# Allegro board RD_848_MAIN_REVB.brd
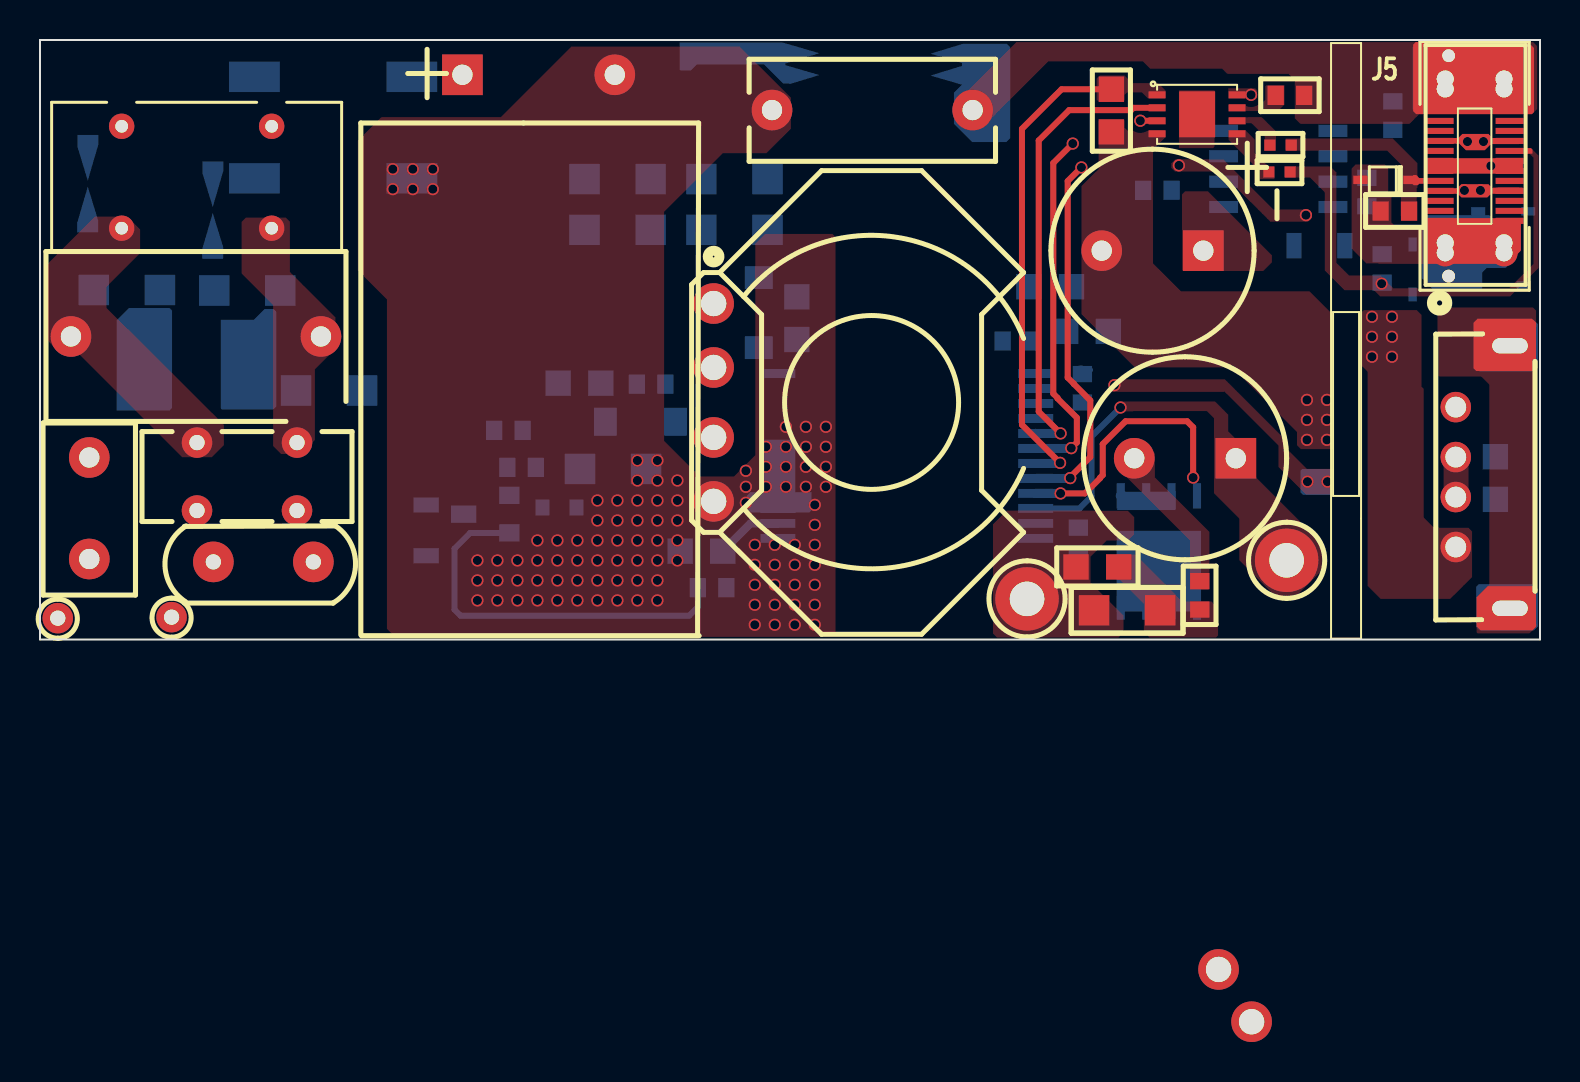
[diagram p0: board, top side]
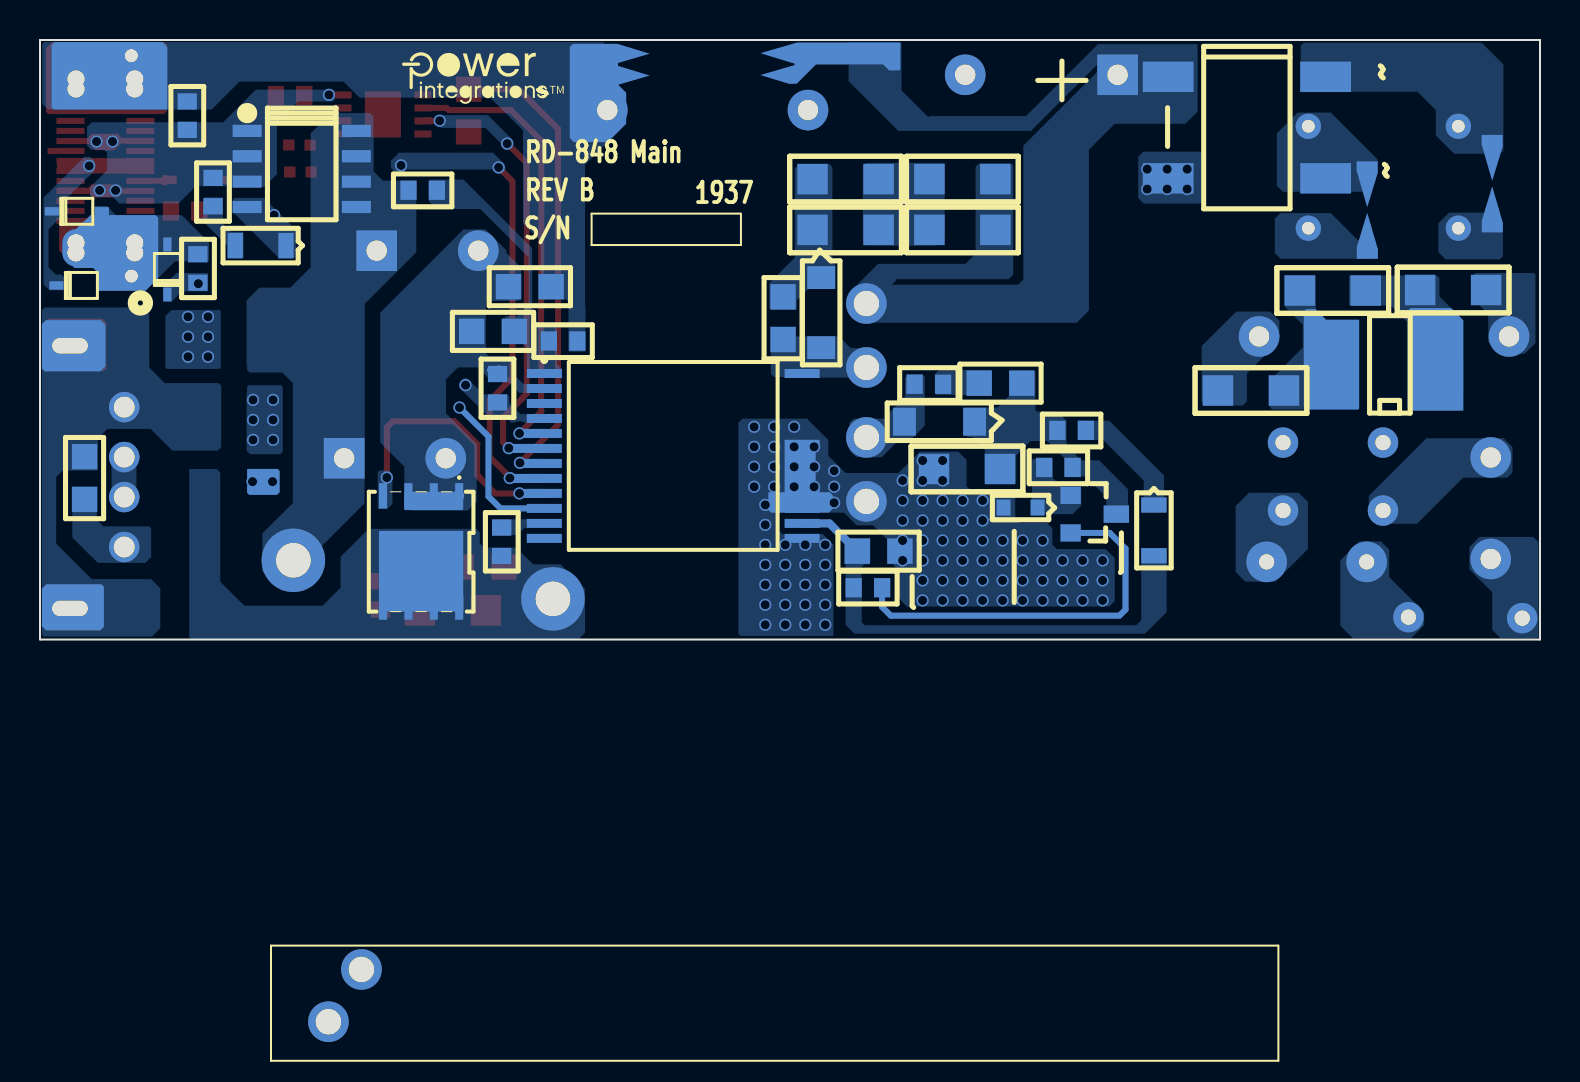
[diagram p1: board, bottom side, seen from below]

Outline 75 x 30 mm; copper layers: TOP, BOTTOM. Coordinates in mm from the lower left corner of the outline.
Outline path: 0,30 0,0 75,0 75,30 0,30

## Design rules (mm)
constraint set DEFAULT: min track width 0.3

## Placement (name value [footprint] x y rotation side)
BR1  DF206ST-G  [PISMDDFS]  18.54 28.16 90 bottom
C1  68 uF  [PIPOLCAPCLYD630LS300040]  21.12 28.26 0 top
C4  10 uF  [PISMC1206]  27 8.53 0 bottom
C5  1  nF  [PISMC1206]  27.23 23.04 0 bottom
C6  4.7 uF  [PISMC0805]  34.14 4.42 180 bottom
C7  47 pF  [PISMC0805]  37.85 17.14 270 bottom
C8  220 pF  [PISMC0603]  29.84 12.78 0 bottom
C11  1000 pF  [PISMC0603]  57.99 2.92 270 top
C12  390 uF  [PIPOLCAPCYLD400LS200040]  58.17 19.46 180 top
C13  390 uF  [PIPOLCAPCYLD400LS200040]  59.79 9.07 180 top
C14  2.2 uF  [PISMC0603]  52.12 13.28 270 bottom
C15  4.7 uF  [PISMC0805]  53.42 15.42 180 bottom
C17  2.2 uF  [PISMC0805]  53.57 25.4 90 top
C27  1 uF  [PISMC0603]  67.64 25.5 90 bottom
C28  560 pF  [PISMC0603]  68.45 21.44 180 top
C29  560 pF  [PISMC0603]  67.11 17.86 90 bottom
C49  0.1 uF  [PISMC0805]  72.77 7.01 90 bottom
CX1  330 nF  [PINP_XCAPRAD15X8P5X14HD040]  14.05 15.16 180 top
CY1  1 nF  [PI_NP475X200LS395D040]  36.6 26.49 0 top
D1  S1ML  [PI_SM_SOD-123_12]  35.94 18.11 270 bottom
D2  S1ML  [PI_SM_SOD-123_12]  28.27 10.9 0 bottom
D3  BAV19WS  [PISMSOD323]  62.7 19.71 0 bottom
D6  MM3Z24VC  [PISMSOD323F]  74.18 17.72 180 bottom
D7  MM3Z24VC  [PISMSOD323F]  74.41 21.43 180 bottom
D8  MM3Z24VC  [PISMSOD323F]  68.52 23 180 top
D9  MM3Z24VC  [PISMSOD323F]  68.63 17.27 90 bottom
F1  3.15 A  [PI_RST_MICROFUSE]  2.46 4.03 90 top
FL1  Hole_70mils  [PI_HOLE_70MIL]  62.33 3.94 0 top
FL2  Hole_70mils  [PI_HOLE_70MIL]  49.35 2.01 0 top
J1  PCB Terminal 30 AWG  [PI_HOLE_30AWG]  0.89 1.07 0 top
J2  PCB Terminal 30 AWG  [PI_HOLE_30AWG]  6.58 1.12 0 top
J4  CON4  [PI_CONN_USB4P_VERT_WURTH]  70.79 8.13 180 top
J5  USB-C  [PI_DX07S024WJ3R400]  69.98 20.95 90 top
L1  550 uH  [PI_4P_LS5W4P5XD10P5MMD40]  10.35 8.15 90 top
L2  20 mH  [PI_TOROID_CMC12P5X7P5_4PV]  11.58 19.38 270 top
NOREF  -  []  -228.6 -144.78 0 top
NOREF#2  -  []  0 30 0 top
NOREF#3  -  []  0 0 90 top
NOREF#4  -  []  -150.78 54.23 0 top
NOREF#5  -  []  57.45 29.27 180 bottom
Q1  MMBTA06LT1G  [PISMSOT23123_1]  23.47 5.33 270 bottom
Q2  AON6220  [PISMPQFN5X6B]  54.04 7.19 0 bottom
Q4  AO4354  [PISMSO8]  64.64 25.45 270 bottom
R3  470 k  [PISMR1206]  27.23 20.5 0 bottom
R4  20  [PISMR1206]  36.37 20.5 180 bottom
R5  20  [PISMR1206]  36.37 23.04 180 bottom
R6  100 k  [PISMR0603]  23.37 8.61 0 bottom
R7  3 k  [PISMR0603]  32.89 2.59 0 bottom
R8  47  [PISMR0603]  24.13 10.46 180 bottom
R11  20  [PISMR0805]  53.94 3.63 180 top
R12  47  [PISMR0603]  51.92 4.18 90 bottom
R13  487 k  [PISMR0603]  56.58 22.48 180 bottom
R14  100  [PISMR0603]  66.34 23.1 270 bottom
R15  10  [PISMR0603]  49.56 14.94 180 bottom
R16  10  [PISMR0805]  25.91 12.83 0 bottom
R20  22  [PISMR0402]  62.56 24.74 180 top
R21  22  [PISMR0402]  62.51 23.39 180 top
R22  12  [PISMR1206]  56.01 1.46 180 top
R23  1 M  [PISMR1206]  2.69 17.49 0 bottom
R24  1 M  [PISMR1206]  12.8 12.46 0 bottom
R25  1 M  [PISMR1206]  8.71 17.46 0 bottom
RS1  0.009  [PISMR0805]  51.57 17.65 180 bottom
RT1  2.5  [PI_RAD150X300LS200D030]  8.67 3.88 0 top
RT2  100 k  [PISMR0603]  63.21 27.23 180 top
T1  RM8  [PI_BOBBIN_RM8_6P_813]  41.58 11.86 0 top
U1  InnoProSize9  [PI_IC_INSOP_24D]  49.78 13.31 180 bottom
U3  VP302  [PI_SM_DFN-8]  55.85 27.25 270 top
U4  CAP200DG *  [PI_IC_SMD_SO8_CAPZERO]  4.97 11.86 90 bottom
ZD1  EDZVT2R10B  [PI_SM_D_SSMINI2P]  25.12 6.6 0 bottom
ZD2  MM3Z47VB  [PISMSOD323]  19.3 6.73 270 bottom

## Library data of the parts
BR1 = DIODE BRIDGE_+-~~
C1 = CAP POL: alternate symbols: (pipolcapclyd630ls3000401000h)
C4 = CAP NP: alternate symbols: (pismc1206_1)
C5-C8 C11 C15 C17 C28 C29 C49 CY1 = CAP NP
C12 C13 = CAP POL: alternate symbols: (pipolcapclyd395x630ls200030h)
C14 C27 = CAP NP: alternate symbols: (pismc0603_1)
CX1 = CAP NP: alternate symbols: (pinp_xcaprad15x8p5x14Hd040H)
D1-D3 = DIODE
D6-D9 ZD1 ZD2 = DIODE_ZENER
F1 = FUSE: alternate symbols: (pirstmicrofusehoz)
FL1 FL2 = FlyingLead
J1 J2 = TERM_1Pin
J4 = CON4_USB_1
J5 = DX07S024WJ3R400: User Part Number: PN; Tolerance: TOL
L1 = TORRID 4P_12_0
L2 = TORRID 4P_12_43a
Q1 = NPN_BEC
Q2 Q4 = FET_N_SGD_123_4_5678
R3-R7 R11 R13-R16 R20-R25 RS1 = R
R8 R12 = R: alternate symbols: (pismr0603_1)
RT1 = THERMISTOR: alternate symbols: (pirad400x300ls200040_h)
RT2 = THERMISTOR
T1 = BRM8_6P/4-2
U1 = DEV_InnoPro
U3 = VP302
U4 = CAPZero

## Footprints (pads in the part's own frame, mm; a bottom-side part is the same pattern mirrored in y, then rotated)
PI_4P_LS5W4P5XD10P5MMD40
  round 1.524 hole 0.762: 1(-1.7,-2.5) 2(1.7,-2.5) 3(1.7,2.5) 4(-1.7,2.5)
PI_BOBBIN_RM8_6P_813
  round 2.032 hole 1.27: 1(-7.9,4.95) 2(-7.9,1.75) 3(-7.9,-1.75) 4(-7.9,-4.95) 5(18.999,-30.988) 6(17.348,-28.372)
PI_CONN_USB4P_VERT_WURTH
  oval 2.54x1.524 hole 1.778x0.762: (-2.71,6.57) (-2.71,-6.57)
  round 1.524 hole 1.041: 1(0,3.5) 2(0,1) 3(0,-1) 4(0,-3.5)
PI_DX07S024WJ3R400
  round 0.85 hole 0.85 unplated: (-1.6,-0.28) (-1.6,-3.22) (-1.1,-0.28) (-1.1,-3.22) (6.6,-0.28) (6.6,-3.22) (7.1,-0.28) (7.1,-3.22)
  oval 1.858x1.358 hole 0.025 unplated: (-1.35,-0.28) (-1.35,-3.22) (6.85,-0.28) (6.85,-3.22)
  round 0.635 hole 0.635: 25(-2.765,-0.45) 26(8.265,-0.45)
  rect 0.305x1.397 smd: A1(0,0) A2(0.5,0) A3(1,0) A4(1.5,0) A5(2,0) A6(2.5,0) A7(3,0) A8(3.5,0) A9(4,0) A10(4.5,0) A11(5,0) A12(5.5,0) B1(5.5,-3.5) B2(5,-3.5) B3(4.5,-3.5) B4(4,-3.5) B5(3.5,-3.5) B6(3,-3.5) B7(2.5,-3.5) B8(2,-3.5) B9(1.5,-3.5) B10(1,-3.5) B11(0.5,-3.5) B12(0,-3.5)
PI_HOLE_30AWG
  round 1.524 hole 0.762: 1(0,0)
PI_HOLE_70MIL
  round 3.175 hole 1.727: 1(0,0.025)
PI_IC_INSOP_24D
  rect 1.75x0.45 smd: 1(0,0) 2(0,-0.75) 3(0,-1.5) 4(0,-2.25) 5(0,-3) 6(0,-3.75) 7(0,-4.5) 8(0,-5.25) 9(0,-6) 10(0,-6.75) 11(0,-7.5) 12(0,-8.25) 13(12.89,-8.25) 14(12.89,-7.5) 15(12.89,-6.75) 24(12.89,0)
  custom 0.438x0.438 smd: 16(12.89,-4.67)
PI_IC_SMD_SO8_CAPZERO
  rect 0.599x2.2 smd: 1(0,0) 2(1.27,0) 3(2.54,0) 4(3.81,0) 5(3.81,5.199) 6(2.54,5.199) 7(1.27,5.199) 8(0,5.199)
PI_NP475X200LS395D040
  round 2.032 hole 1.016: 1(0,0) 2(10.033,0)
PI_RAD150X300LS200D030
  round 2.032 hole 0.762: 1(0,0) 2(5,0)
PI_RST_MICROFUSE
  round 2.032 hole 1.016: 1(0,0) 2(5.08,0)
PI_SM_D_SSMINI2P
  rect 0.699x0.8 smd: 1(0,0) 2(1.7,0)
PI_SM_DFN-8
  rect 0.35x0.85 smd: 1(0,0) 2(0.65,0) 3(1.3,0) 4(1.95,0) 5(1.95,4) 6(1.3,4) 7(0.65,4) 8(0,4)
  rect 2.3x1.8 smd: 9(0.975,2)
PI_SM_SOD-123_12
  rect 1.143x1.397 smd: 1(0,0) 2(3.505,0)
PI_TOROID_CMC12P5X7P5_4PV
  round 1.27 hole 0.635: 1(-1.2,0) 2(-6.3,0) 3(-6.3,-7.5) 4(-1.2,-7.5)
PINP_XCAPRAD15X8P5X14HD040
  round 2.032 hole 1.016: 1(0,0) 2(12.5,0)
PIPOLCAPCLYD630LS300040
  rect 2.032x2.032 hole 1.016: 1(0,0)
  round 2.032 hole 1.016: 2(7.62,0)
PIPOLCAPCYLD400LS200040
  rect 2.032x2.032 hole 1.016: 1(0,0)
  round 2.032 hole 1.016: 2(5.08,0)
PISMC0603
  rect 0.813x0.965 smd: 1(0,0) 2(1.422,0)
PISMC0805
  rect 1.27x1.27 smd: 1(0,0) 2(2.134,0)
PISMC1206
  rect 1.524x1.524 smd: 1(0,0) 2(3.302,0)
PISMDDFS
  rect 1.524x2.54 smd: 1(0,0.051) 2(-5.08,0.051) 3(0,-7.823) 4(-5.08,-7.823)
PISMPQFN5X6B
  rect 0.406x1.27 smd: 1(0,0) 2(1.27,0) 3(2.54,0) 4(3.81,0)
  rect 0.406x1.219 smd: 5(3.81,5.588) 6(2.54,5.588) 7(1.27,5.588) 8(0,5.588)
PISMR0402
  rect 0.559x0.559 smd: 1(0,0) 2(1.067,0)
PISMR0603
  rect 0.813x0.965 smd: 1(0,0) 2(1.422,0)
PISMR0805
  rect 1.27x1.27 smd: 1(0,0) 2(2.134,0)
PISMR1206
  rect 1.524x1.524 smd: 1(0,0) 2(3.302,0)
PISMSO8
  rect 0.61x1.448 smd: 1(0,0) 2(1.27,0) 3(2.54,0) 4(3.81,0) 5(3.81,5.461) 6(2.54,5.461) 7(1.27,5.461) 8(0,5.461)
PISMSOD323
  rect 0.762x1.27 smd: 1(0,0) 2(2.54,0)
PISMSOD323F
  rect 0.701x0.419 smd: 1(0,0) 2(2.5,0)
PISMSOT23123_1
  rect 0.864x1.016 smd: 1(-1.88,0) 2(0,0)
  rect 0.864x1.27 smd: 3(-0.94,2.286)

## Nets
+5V BUS: C49.1 J4.1(VBUS)
GND: C11.1 C12.2 C13.2 C14.1 C15.1 C17.1 C49.2 J4.4 Q2.1 Q2.2 Q2.3(S3) RS1.1 U1.2 U3.4
GND_SIGNAL: C27.2 C28.2 C29.2 CY1.2 D6.2 D7.2 D8.2 D9.2 J5.A1 J5.A12 J5.B1 J5.B12 R15.2 RS1.2 RT2.1
BPS: C14.2 U1.4
FL2: FL2.1 Q2.5 Q2.6 Q2.7 Q2.8 R11.2 R12.1 R22.2
NC3: U1.3
S1: C27.1 J5.A4 J5.A9 J5.B4 J5.B9 Q4.1 Q4.2 Q4.3(S3) R14.1 U3.8
VDC-OUT: C12.1 C13.1 FL1.1 Q4.5 Q4.6 Q4.7 Q4.8 R13.1 U1.10(VOUT)
N12696113: BR1.1 C1.1 C5.1 R3.1 T1.1
N12696321: C7.2 D1.2 T1.2 U1.24
N12696371: C5.2 R3.2 R4.2 R5.2
N12696403: BR1.2 C1.2 C4.2 C6.2 CY1.1 T1.4 U1.13 U1.16 ZD1.2
N12696521: BR1.3 L2.3
N12696529: BR1.4 L2.2
N12696569: C7.1 D1.1 R4.1 R5.1
N12696753: C8.1 R16.2
N12696761: C8.2 D2.2 T1.3
N12696785: C11.2 R11.1 R22.1
N12696901: C4.1 D2.1 Q1.3 R6.1 R8.1 R16.1
N12697221: C15.2 R13.2 R15.1 U1.1
N12697259: Q2.4 U1.9
N12697307: R12.2 U1.11
N12697427: Q1.1 R6.2 ZD1.1
N12697475: R8.2 ZD2.1
N12697497: J2.1 RT1.1
N12697517: Q1.2(EMITTER) R7.1
N12697613: C6.1 R7.2 U1.14 ZD2.2
N12856532: L1.1 RT1.2
N12860506: CX1.1 L1.2 L2.1 R24.2
N12860535: CX1.2 L1.3 L2.4 R23.1
N12939410: C17.2 U1.7 U3.1(VCC)
N12939527: D3.1 Q4.4 U1.8
N12962608: D3.2 R14.2
N12962926: D6.1 D7.1 J5.A6 J5.A7 J5.B6 J5.B7
N12962950: C28.1 D8.1 J5.A5 R20.1
N12963022: RT2.2 U3.7
N12963250: C29.1 D9.1 J5.B5 R21.1
N12963278: R20.2 U3.6
N12963330: R21.2 U3.5
N12967856: U1.5 U3.2
N12967863: U1.6 U3.3
N12982735: F1.2 L1.4
N12983558: F1.1 J1.1
N12984078: R23.2 R25.1 U4.2
N12984082: R24.1 R25.2 U4.7
N13015620: J4.2 J4.3

Pads without a net: J5 25 26 A2 A3 A8 A10 A11 B2 B3 B8 B10 B11; T1 5 6; U1 12 15; U3 9; U4 1 3 4 5 6 8

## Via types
v1: diameter 0.61, hole 0.457, TOP to BOTTOM, 134 vias

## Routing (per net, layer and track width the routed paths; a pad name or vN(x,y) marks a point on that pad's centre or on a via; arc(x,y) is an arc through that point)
+5V BUS:
  vias: v1(66.6,16.15) v1(66.6,15.15) v1(66.6,14.15) v1(67.6,16.15) v1(67.6,15.15) v1(67.6,14.15)
GND: length 0.8
  BOTTOM w0.3: 52.5,13.49 52.07,13.49 52.04,13.46
  BOTTOM w0.5: 54.14,7.19 Q2.1
  BOTTOM w0.508: C14.1 52.12,13.39 52.04,13.46
  vias: v1(63.35,11.99) v1(63.35,10.99) v1(63.35,9.99) v1(64.35,11.99) v1(64.35,10.99) v1(64.35,9.99)
BPS:
  vias: v1(53.72,12.73) v1(63.37,7.9) v1(64.37,7.9)
S1:
  vias: v1(60.55,27.25) v1(71.22,22.47) v1(71.37,24.92) v1(72.02,22.47) v1(72.17,24.92)
VDC-OUT: length 8.1
  BOTTOM w0.3: U1.10 51.97,6.56 52.58,7.16 52.58,10.16 v1(54.03,11.61)
N12696403:
  vias: v1(17.64,23.54) v1(17.64,22.54) v1(18.64,23.54) v1(18.64,22.54) v1(19.64,23.54) v1(19.64,22.54) v1(21.87,3.96) v1(21.87,2.96) v1(21.87,1.96) v1(22.87,3.96) v1(22.87,2.96) v1(22.87,1.96) v1(23.87,3.96) v1(23.87,2.96) v1(23.87,1.96) v1(24.87,4.96) v1(24.87,3.96) v1(24.87,2.96) v1(24.87,1.96) v1(25.87,4.96) v1(25.87,3.96) v1(25.87,2.96) v1(25.87,1.96) v1(26.87,4.96) v1(26.87,3.96) v1(26.87,2.96) v1(26.87,1.96) v1(27.87,6.96) v1(27.87,5.96) v1(27.87,4.96) v1(27.87,3.96) v1(27.87,2.96) v1(27.87,1.96) v1(28.87,6.96) v1(28.87,5.96) v1(28.87,4.96) v1(28.87,3.96) v1(28.87,2.96) v1(28.87,1.96) v1(29.87,8.96) v1(29.87,7.96) v1(29.87,6.96) v1(29.87,5.96) v1(29.87,4.96) v1(29.87,3.96) v1(29.87,2.96) v1(29.87,1.96) v1(30.87,8.96) v1(30.87,7.96) v1(30.87,6.96) v1(30.87,5.96) v1(30.87,4.96) v1(30.87,3.96) v1(30.87,2.96) v1(30.87,1.96) v1(31.87,7.96) v1(31.87,6.96) v1(31.87,5.96) v1(31.87,4.96) v1(31.87,3.96) v1(35.29,8.44) v1(35.29,7.64) v1(35.29,6.84) v1(35.74,4.74) v1(35.74,3.74) v1(35.74,2.74) v1(35.74,1.74) v1(35.74,0.74) v1(36.29,9.64) v1(36.29,8.64) v1(36.29,7.64) v1(36.74,4.74) v1(36.74,3.74) v1(36.74,2.74) v1(36.74,1.74) v1(36.74,0.74) v1(37.29,10.64) v1(37.29,9.64) v1(37.29,8.64) v1(37.29,7.64) v1(37.74,4.74) v1(37.74,3.74) v1(37.74,2.74) v1(37.74,1.74) v1(37.74,0.74) v1(38.29,10.64) v1(38.29,9.64) v1(38.29,8.64) v1(38.29,7.64) v1(38.74,6.74) v1(38.74,5.74) v1(38.74,4.74) v1(38.74,3.74) v1(38.74,2.74) v1(38.74,1.74) v1(38.74,0.74) v1(39.29,10.64) v1(39.29,9.64) v1(39.29,8.64) v1(39.29,7.64)
N12697259: length 12.9
  TOP w0.3: v1(51.03,7.31) 52.24,7.31 53.01,8.08 53.01,8.1 53.14,8.23 53.14,9.78 54.28,10.92 57.35,10.92 57.66,10.62 v1(57.66,8.1)
  BOTTOM w0.45: U1.9 v1(51.03,7.31)
N12697517: length 19.6
  BOTTOM w0.3: Q1.2 21.51,5.33 20.73,4.55 20.73,1.49 21.03,1.19 32.46,1.19 32.89,1.63 R7.1
N12697613: length 3.3
  BOTTOM w0.4: C6.1 35.53,5.81 U1.14
N12939410: length 24
  TOP w0.3: v1(51,8.84) 49.1,10.74 49.1,25.55 51.08,27.53 C17.2
  BOTTOM w0.45: U1.7 50.97,8.81 v1(51,8.84)
N12939527: length 18.4
  TOP w0.3: v1(52.07,23.62) 51.38,22.94 51.38,13.11 51.69,12.8 51.69,12.79 52.51,11.96 52.51,9.13 51.51,8.13 v1(51.51,8.08)
  BOTTOM w0.45: v1(51.51,8.08) 51.49,8.06 U1.8
  vias: v1(56.95,23.72) v1(63.3,21.23)
N12962926:
  vias: v1(72.54,23.7)
N12963250:
  vias: v1(67.08,17.81)
N12967856: length 22.9
  TOP w0.3: v1(51.03,10.31) 49.94,11.4 49.94,24.97 51.46,26.49 54.56,26.49 54.67,26.6 U3.2
  BOTTOM w0.45: v1(51.03,10.31) 49.79,10.31 U1.5
N12967863: length 18.9
  TOP w0.3: v1(51.64,24.82) 50.66,23.84 50.66,12.3 50.88,12.09 50.88,12.06 51.84,11.1 51.84,9.86 v1(51.56,9.58) ; v1(55.02,25.96) 55.02,25.95 U3.3
  BOTTOM w0.45: v1(51.56,9.58) 51.55,9.56 U1.6

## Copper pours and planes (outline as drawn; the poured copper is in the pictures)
+5V BUS on TOP: 69.08,12.65 69.19,12.53 69.19,6.1 69.7,5.59 71.42,5.59 71.6,5.41 71.6,3.12 70.51,2.03 67.03,2.03 66.38,2.68 66.38,13.4 66.01,13.77 66.01,16.31 66.19,16.48 68.83,16.48 69.08,16.24
+5V BUS on BOTTOM: 72.11,3.84 69.72,3.84 69.44,4.11 69.44,5.56 69.55,5.66 71.83,5.66 72.16,5.99 72.16,7.52 72.26,7.62 73.28,7.62 73.38,7.52 73.38,5.11
+5V BUS on BOTTOM: 65.96,16.43 66.01,16.48 68.43,16.48 68.73,16.18 68.73,13.61 68.66,13.54 66.04,13.54 65.96,13.61
GND on BOTTOM (solid shape): 56.78,6.48 53.86,6.48 53.86,7.39 56.78,7.39
GND on BOTTOM (solid shape): 74.9,15.77 74.9,13.56 74.75,13.41 71.98,13.41 71.73,13.67 71.73,15.75 71.96,15.98 74.7,15.98
GND on BOTTOM (solid shape): 74.9,2.54 74.9,0.66 74.7,0.46 71.98,0.46 71.81,0.64 71.81,2.64 71.93,2.77 74.68,2.77
GND on TOP: 57.51,2.51 57.51,4.95 53.98,8.48 53.98,9.5 54.41,9.93 55.13,9.93 55.74,9.32 55.74,8.12 58.47,5.38 58.47,2.54 58.42,2.49 57.53,2.49
GND on TOP: 64.64,9.53 63.04,9.53 62.85,9.72 62.85,10.38 59.61,13.61 54.74,13.61 52.07,16.28 52.07,22.68 52.93,23.55 52.93,25.98 54.2,25.98 54.23,25.96 54.23,25.6 54.38,25.45 55.4,25.45 55.42,25.48 56.21,25.48 56.26,25.43 56.26,25.12 55.65,24.51 55.65,18.82 57.05,17.42 63.47,17.42 64.64,16.26
GND on BOTTOM: 53.11,13.61 52.4,12.9 51.61,12.9 51.05,12.34 49,12.34 48.97,12.37 48.97,12.7 49.05,12.78 50.83,12.78 51.28,13.23 51.31,13.23 51.31,13.87 51.61,14.17 52.55,14.17 52.7,14.33 52.7,16.89 52.65,16.94 51.08,16.94 50.95,17.07 50.95,18.62 51.69,19.35 51.69,19.48 52.73,20.52 53.82,20.52 57.99,16.36 57.99,9.86 56.78,8.65 56.78,6.82 56.41,6.45 53.62,6.45 53.16,6.91 53.16,9.78 54.7,11.32 54.7,13.02 54.1,13.61
GND on BOTTOM: 66.07,12.83 68.76,12.83 69.54,13.61 69.54,16.33 69.82,16.61 74.78,16.61 74.9,16.48 74.9,0.25 74.8,0.15 69.39,0.15 68.99,0.56 68.99,2.57 69.44,3.02 72.42,3.02 74.19,4.8 74.19,8.13 73.84,8.48 73.69,8.48 73.67,8.46 72.16,8.46 72.11,8.51 72.11,10.06 71.63,10.54 69.47,10.54 68.38,9.45 66.12,9.45 65.94,9.63 65.94,12.7
GND on BOTTOM: 64.67,9.45 64.49,9.27 62.99,9.27 62.87,9.4 62.87,12.65 62.94,12.73 64.57,12.73 64.64,12.65 64.64,12.37 64.67,12.34
GND_SIGNAL on TOP (solid shape): 74.7,29.59 74.7,26.39 74.6,26.29 68.81,26.29 68.66,26.44 68.66,29.77 68.78,29.9 74.4,29.9
GND_SIGNAL on TOP (solid shape): 74.04,21.03 74.04,19.46 73.38,18.8 69.27,18.8 69.22,18.85 69.22,20.45 69.32,20.55 69.32,21.08 73.99,21.08
GND_SIGNAL on BOTTOM (solid shape): 74.42,29.74 74.42,26.62 74.32,26.52 68.63,26.52 68.63,29.64 68.88,29.9 74.27,29.9
GND_SIGNAL on BOTTOM (solid shape): 72.77,20.93 72.8,20.93 73.66,20.07 73.66,18.97 73.28,18.59 72.34,18.59 72.11,18.36 72.11,17.45 69.72,17.45 69.09,18.08 69.09,21.11 69.22,21.23 72.47,21.23
GND_SIGNAL on BOTTOM (solid shape): 48.51,29.64 48.51,25.09 48.31,24.89 46.61,24.89 45.69,25.81 45.69,27.36 46.1,27.76 44.52,28.22 46.1,28.7 46.1,28.85 44.52,29.31 46.13,29.8 48.35,29.8
GND_SIGNAL on TOP: 74.65,29.9 74.85,29.69 74.85,26.54 74.63,26.31 68.99,26.31 68.48,25.81 63.02,25.81 62.74,26.09 62.74,27.99 62.42,28.31 59.36,28.31 59.11,28.56 55.51,28.56 55.14,28.93 50.42,28.93 47.17,25.68 46.18,25.68 45.77,26.09 45.77,26.85 48.82,29.9
GND_SIGNAL on TOP: 67.41,22.38 67.56,22.23 67.56,20.88 67.84,20.6 69.06,20.6 69.55,21.08 73.99,21.08 74.04,21.03 74.04,19.46 73.38,18.8 66.93,18.8 66.9,18.82 66.32,18.82 65.58,19.56 65.58,23.57 65.79,23.77 67.23,23.77 67.41,23.6
GND_SIGNAL on BOTTOM: 47.75,16.74 47.75,23.75 45.69,25.81 45.69,27.36 46.46,28.12 46.46,29.51 46.84,29.9 74.78,29.9 74.88,29.79 74.88,26.8 74.6,26.52 66.42,26.52 65.02,27.91 59.82,27.91 59.02,27.11 52.49,27.11 50.85,25.48 50.85,20.83 49.97,19.95 49.97,17.16 49.83,17.02 48.69,17.02 48.58,16.9 48.58,15.41 48.59,15.39 48.59,14.45 48.54,14.4 47.78,14.4 47.73,14.45 47.73,16.71
GND_SIGNAL on BOTTOM: 66.57,18.92 66.55,18.95 66.55,19.86 67.92,21.23 71.2,21.23 71.65,21.69 72.26,21.69 72.26,21.46 73.66,20.07 73.66,18.97 73.25,18.57 72.31,18.57 72.06,18.31 72.06,17.5 72.12,17.44 69.74,17.44 68.25,18.92
BPS on BOTTOM (solid shape): 64.64,8.51 64.64,7.34 64.54,7.24 63.14,7.24 63.02,7.37 63.02,8.43 63.12,8.53 64.62,8.53
BPS on TOP: 59.25,13.02 62.38,9.88 62.38,9.5 63.35,8.53 64.59,8.53 64.67,8.46 64.67,7.26 63.3,7.26 61.93,8.64 61.93,9.7 59.22,12.41 59.21,12.4 53.57,12.4 53.44,12.52 53.44,12.85 53.61,13.02
BPS on BOTTOM: 48.95,11.28 50.98,11.28 51.54,11.84 51.54,12.17 51.64,12.27 52.83,12.27 53.64,13.08 53.82,13.08 54.05,12.85 54.05,12.62 52.63,11.2 51.79,11.2 51.44,10.85 49.02,10.85 48.92,10.95 48.92,11.25
FL2 on BOTTOM (solid shape): 58.05,1.4 53.84,1.4 53.84,5.44 58.05,5.44
FL2 on TOP: 47.65,0.3 47.65,5.77 48.34,6.45 52.7,6.45 52.72,6.44 54.39,6.44 54.71,6.12 54.71,5.26 54.41,4.95 53.34,4.95 52.53,4.14 52.53,2.84 54.18,1.19 54.18,0.36 53.92,0.1 47.85,0.1
FL2 on BOTTOM: 48.97,3.76 50.34,3.76 51.18,4.6 52.81,4.6 53.01,4.8 53.01,5.36 53.19,5.54 58.57,5.54 59.97,4.14 59.97,2.59 60.87,1.69 64.78,1.69 65.99,2.9 65.99,8.36 66.17,8.53 67.49,8.53 67.54,8.48 67.54,0.1 67.41,-0.03 48.11,-0.03 47.75,0.33 47.75,2.54
Net_3 on TOP (solid shape): 74.8,0.64 74.63,0.46 72.03,0.46 71.83,0.66 71.83,2.11 72.39,2.67 74.8,2.67
Net_3 on TOP (solid shape): 74.8,15.85 74.8,13.56 74.68,13.44 71.81,13.44 71.68,13.56 71.68,15.85 71.88,16.05 74.6,16.05
Net_3 on TOP: 74.8,0.64 74.47,0.3 71.88,0.3 71.83,0.36 71.83,2.11 72.47,2.74 72.47,12.75 72.06,13.16 69.98,13.16 69.88,13.26 69.88,16.33 70.15,16.61 74.65,16.61 74.8,16.46
Net_54 on TOP: 58.72,27.48 58.72,24.66 58.65,24.59 56.95,24.59 56.95,27.48
Net_55 on BOTTOM (solid shape): 11.26,11.56 9.08,11.56 9.08,12.17 9.59,12.17 9.59,15.37 9.08,15.37 9.08,15.98 11.26,15.98
S1 on TOP (solid shape): 72.62,25.1 73.94,25.1 73.96,25.07 73.96,24.82 73.94,24.79 72.54,24.79 72.24,24.49 71.3,24.49 70.97,24.82 69.57,24.82 69.55,24.84 69.55,25.1 70.92,25.1 71.12,25.3 72.42,25.3
S1 on TOP (solid shape): 72.59,22.61 74.12,22.61 74.14,22.58 74.14,22.3 72.54,22.3 72.36,22.12 71.07,22.12 70.89,22.3 69.65,22.3 69.62,22.33 69.62,22.58 70.87,22.58 71.07,22.78 72.42,22.78
S1 on BOTTOM: 65.84,25.88 72.42,25.88 72.64,25.65 72.64,24.71 72.44,24.51 71.81,24.51 71.65,24.36 71.65,23.47 72.49,22.63 72.49,22.23 72.42,22.15 71.37,22.15 71.04,21.82 68.07,21.82 67.21,22.68 65.56,22.68 65.52,22.64 63.79,22.64 63.16,23.28 63.16,25.86 62.09,26.92 60.35,26.92 60.27,27 60.27,27.46 60.33,27.51 64.21,27.51
VDC-OUT on TOP: 57.1,18.49 57.1,22.28 57.25,22.43 58.39,22.43 61.59,19.23 61.59,18.87 61.16,18.44 57.15,18.44
VDC-OUT on TOP: 64.1,4.81 64.1,3.47 62.79,2.16 61.77,2.16 59.97,3.96 59.97,6.05 58.7,7.32 58.7,11.07 58.34,11.43 54.66,11.43 54.65,11.42 54.19,11.42 54.1,11.33 53.98,11.33 53.75,11.56 53.75,11.73 53.92,11.91 58.75,11.91 59.41,11.25 59.41,10.41 59.77,10.06 60.81,10.06 60.81,8.1
VDC-OUT on BOTTOM: 58.5,26.34 60.45,26.34 61.47,25.32 61.47,18.62 62.48,17.6 64.03,17.6 64.67,16.97 64.67,13.72 64.64,13.72 64.64,13.49 64.52,13.36 62.89,13.36 62.36,12.83 62.36,6.83 63.88,5.31 63.88,3.39 62.94,2.45 61.75,2.45 60.9,3.3 60.9,4.69 58.78,6.81 58.78,7.98 58.76,7.99 58.76,16.8 56.18,19.38 56.18,22.96 57.86,22.96 58.32,23.42 58.32,26.16
N12696113 on BOTTOM (solid shape): 38.97,29.34 37.27,28.82 37.27,28.74 38.97,28.24 37.49,27.79 37.47,27.81 37.16,27.81 36.2,28.78 32.85,28.78 32.54,28.47 32.03,28.47 31.98,28.52 31.98,29.87 37.14,29.87
N12696113 on BOTTOM: 17.17,29.79 22.1,29.79 25.7,26.19 30.53,26.19 30.58,26.14 31.93,27.48 31.93,29.84 31.95,29.87 34.54,29.87 34.57,29.84 34.57,27.94 32.08,25.45 25.45,25.45 21.79,29.11 21.67,29.11 21.67,28.85 21.69,28.83 21.72,28.83 25.83,24.71 25.83,18.01 26.09,17.75 32.41,17.75 32.21,17.96 32.21,18.03 26.57,18.03 26.34,18.26 26.34,23.72 26.44,23.83 28.04,23.83 28.22,23.65 28.22,19.41 28.17,19.35 28.73,18.8 33.1,18.8 34.14,17.75 34.12,17.74 34.47,17.4 34.47,16.26 34.06,15.85 23.16,15.85 22.56,16.46 22.56,24.51 21.26,25.81 17.73,25.81 17.12,26.42 17.12,29.74
N12696321 on BOTTOM: 33.35,14.58 34.47,14.58 35.05,15.16 37.08,15.16 37.11,15.14 37.21,15.24 37.21,15.57 38.43,15.57 38.46,15.54 38.46,13.28 38.3,13.13 37.77,13.13 37.74,13.11 34.57,13.11 34.21,12.75 33.2,12.75 32.72,13.23 32.72,13.94
N12696371 on BOTTOM: 33.73,19.71 30.18,19.71 29.77,20.12 29.77,23.85 33.68,23.85 33.86,23.67 33.86,19.96 33.73,19.84
N12696403 on BOTTOM (solid shape): 38.58,6.48 38.46,6.35 35.56,6.35 35.36,6.55 35.36,7.21 35.51,7.37 38.58,7.37
N12696403 on TOP: 17.35,0.53 17.75,0.13 39.67,0.13 39.78,0.23 39.78,20.14 39.62,20.29 36.25,20.29 35.76,19.81 35.76,9.22 34.7,8.15 32.99,8.15 31.2,9.94 31.2,21.4 34.14,24.33 36.32,24.33 37.54,25.55 37.54,27.11 34.99,29.67 26.57,29.67 23.04,26.14 17.07,26.14 15.89,24.96 15.89,18.48 17.35,17.02
N12696403 on BOTTOM: 20.09,22.1 19.81,21.82 16.97,21.82 16.94,21.84 16.94,24.36 16.99,24.41 19.84,24.41 20.09,24.16
N12696403 on BOTTOM: 36.65,11.05 39.88,11.05 40.08,10.85 40.08,0.28 39.98,0.18 35.38,0.18 35.33,0.23 35.33,4.75 35.86,5.28 37.9,5.28 38.05,5.44 38.05,6.32 38.02,6.35 34.8,6.35 34.16,5.71 33.35,5.71 32.56,4.93 32.56,3.96 32.05,3.45 32.05,2.06 31.56,1.56 21.63,1.56 21.26,1.93 21.26,4.06 21.72,4.52 24.16,4.52 24.38,4.75 24.38,5.56 24.66,5.84 26.01,5.84 26.24,6.07 26.24,7.14 26.37,7.26 26.44,7.26 26.45,7.25 26.47,7.26 28.27,7.26 28.69,7.68 28.68,7.7 28.68,8.99 29.08,9.4 31.01,9.4 32.08,8.33 34.72,8.33 35.59,9.19 35.59,9.98
N12696521 on BOTTOM (solid shape): 2.92,24.79 2.39,22.96 1.87,24.66 1.87,25.25 2.92,25.25
N12696521 on BOTTOM: 11.96,27.41 6.12,27.41 5.21,26.49 5.21,25.22 4.29,24.31 1.98,24.31 1.83,24.46 1.83,28.78 2.91,29.86 11.82,29.86 11.96,29.72
N12696529 on BOTTOM (solid shape): 9.17,23.47 8.64,21.64 8.12,23.34 8.12,23.93 9.17,23.93
N12696529 on BOTTOM: 13.16,25.32 13.16,22.71 12.85,22.4 8.86,22.4 8.85,22.42 8.67,22.42 8.36,22.73 8.36,23.06 8.13,23.29 8.13,24.03 10.46,26.37 12.12,26.37
N12696569 on BOTTOM: 37.16,16.54 37.16,16.97 36.58,17.55 35.26,17.55 35.23,17.58 35.23,18.8 35.38,18.95 35.38,23.65 35.53,23.8 37.03,23.8 37.26,23.57 37.26,19.1 38.53,17.83 38.53,16.59 38.46,16.51 37.19,16.51
N12696753 on BOTTOM: 27.46,13.49 30.05,13.49 30.25,13.28 30.25,12.32 30.18,12.24 27.46,12.24 27.43,12.27 27.43,13.46
N12696761 on BOTTOM: 30.76,10.69 31.47,9.98 32.05,9.98 32.92,9.12 33.96,9.12 33.97,9.13 34.2,9.13 34.52,9.45 34.52,10.85 34.32,11.05 32.84,11.05 31.75,12.14 31.75,13.11 31.6,13.26 30.89,13.26 30.76,13.13
N12696785 on TOP: 53.64,4.24 54.79,4.24 56.77,2.26 56.77,2.24 57.1,1.91 58.57,1.91 58.9,1.57 58.9,0.2 58.8,0.1 55.47,0.1 55.19,0.38 55.19,1.78 53.98,3 53.59,3 53.59,3.86 53.57,3.89 53.57,4.17
N12696901 on BOTTOM: 25.3,13.46 26.39,13.46 26.52,13.34 26.52,12.32 26.47,12.27 27.13,11.61 28.78,11.61 28.8,11.58 28.8,10.31 28.63,10.13 28.4,10.13 27.76,9.5 27.76,7.9 27.66,7.8 26.26,7.8 26.19,7.87 26.19,9.22 25.48,9.93 24.64,9.93 23.8,9.09 23.8,8.15 22.71,8.15 21.69,7.14 21.69,5.97 21.56,5.84 20.7,5.84 20.6,5.94 20.6,7.52 22.05,8.97 22.94,8.97 23.67,9.7 23.67,10.95 24.13,11.4 25.15,11.4 25.22,11.48 25.22,13.39
N12697221 on BOTTOM: 48.92,13.56 49.16,13.8 49.16,15.56 49.35,15.75 50.01,15.75 50.39,16.13 50.39,19.58 53.82,23.01 55.47,23.01 55.55,22.94 55.55,21.92 55.17,21.54 52.98,21.54 50.57,19.13 50.57,16.76 51.16,16.18 51.69,16.18 51.87,16 51.87,14.99 51.66,14.78 50.85,14.78 50.65,14.58 50.65,13.11 50.62,13.08 48.95,13.08 48.92,13.11
N12697259 on BOTTOM: 57.56,8.46 58.01,8.46 58.12,8.36 58.12,6.55 58.09,6.53 57.63,6.53 57.38,6.78 57.38,8.28
N12697307 on BOTTOM: 49.05,6.02 52.35,6.02 52.37,5.99 52.37,5.28 52.32,5.23 51.13,5.23 50.77,5.59 49.23,5.59 49,5.82 49,5.97
N12697427 on BOTTOM: 22.99,7.65 23.93,7.65 24.36,8.08 24.36,8.97 24.43,9.04 25.32,9.04 25.4,8.97 25.4,6.43 25.25,6.27 23.37,6.27 22.94,6.71 22.94,7.59
N12697475 on BOTTOM: 18.8,6.48 18.8,8.2 21.54,10.95 23.09,10.95 23.09,9.98 22.15,9.98 22.07,10.06 21.92,10.06 19.81,7.95 19.81,6.4 18.87,6.4
N12697497 on BOTTOM: 7.95,4.9 7.54,4.5 7.54,3.12 5.79,1.37 5.79,0.71 6.45,0.05 9.35,0.05 9.98,0.69 9.98,3.96 9.04,4.9
N12697613 on BOTTOM: 33.5,5.08 34.7,5.08 34.72,5.05 34.72,2.13 34.71,2.12 34.72,2.11 34.72,0.74 34.28,0.29 19.75,0.29 18.67,1.37 18.67,4.45 18.75,4.52 19.84,4.52 19.94,4.42 19.94,0.97 20.19,0.71 33.76,0.71 33.91,0.86 33.91,2.13 33.93,2.13 33.93,3.61 33.78,3.76 33.53,3.76 33.48,3.81 33.48,5.05
N12856532 on BOTTOM: 11.61,6.88 11.61,4.52 13.23,2.9 14.73,2.9 15.21,3.38 15.21,6.68 14.55,7.34 12.06,7.34
N12860506 on BOTTOM (solid shape): 9.16,19.64 9.16,19.05 8.1,19.05 8.1,19.51 8.64,21.34
N12860506 on TOP: 11.66,16.74 10.08,18.31 10.08,20.9 10.29,21.11 12.29,21.11 12.5,20.9 12.5,18.39 14.77,16.12 14.77,14.54 13.74,13.51 13.74,9.98 13.04,9.28 12.05,9.28 11.66,9.68
N12860506 on BOTTOM: 8.27,19.05 8.27,19.85 8.41,19.99 9.12,19.99 10.46,21.34 12.98,21.34 13.26,21.06 13.26,19.33 12.98,19.05
N12860506 on BOTTOM: 15.19,16.41 16.92,14.68 16.92,11.91 16.71,11.71 14.86,11.71 14.66,11.91 14.66,13.31 13.03,14.94 13.03,15.95 13.49,16.41
N12860535 on BOTTOM (solid shape): 2.91,20.96 2.91,20.37 1.86,20.37 1.86,20.83 2.39,22.66
N12860535 on TOP: 1.02,14.33 0.41,14.94 0.41,18.82 2.74,21.16 4.37,21.16 5,20.52 5,19.33 3.33,17.65 3.33,16.59 4.37,15.54 4.39,15.54 9.19,10.74 9.19,9.73 8.59,9.12 7.11,9.12 1.91,14.33
N12860535 on BOTTOM: 5.08,20.83 5.08,19.38 4.72,19.02 2.01,19.02 1.85,19.18 1.85,20.83 2.39,21.36 4.55,21.36
N12860535 on BOTTOM: 0.23,14.83 0.23,18.26 0.3,18.34 3.28,18.34 3.28,16.97 2.59,16.28 2.59,14.91 1.98,14.3 0.76,14.3
N12939410 on TOP: 52.98,28.22 54.23,28.22 54.61,27.84 55.91,27.84 56.29,27.46 56.29,27.1 56.24,27.05 55.42,27.05 55.09,27.38 54.36,27.38 54.23,27.25 54.23,26.97 52.83,26.97 52.83,28.07
N12939527 on TOP: 56.77,24.03 59.16,24.03 61.67,21.51 63.3,21.51 63.32,21.54 63.37,21.54 63.58,21.34 63.58,21.08 63.4,20.9 61.52,20.9 59,23.42 56.74,23.42 56.57,23.6 56.57,23.83
N12939527 on BOTTOM: 62.2,19.18 62.2,20.5 63.8,22.1 65.25,22.1 65.38,21.97 65.38,21.41 63.07,19.1 63.07,19.08 62.31,19.08
N12939527 on BOTTOM: 51.74,23.5 51.74,23.75 52.35,24.36 57.05,24.36 57.45,23.95 57.45,23.6 57.28,23.42 56.77,23.42 56.67,23.52 52.3,23.52 52.1,23.32 51.92,23.32
N12962608 on BOTTOM: 64.82,19.1 64.82,20.35 64.87,20.4 65.46,20.4 65.86,20.8 65.86,22.12 66.8,22.12 66.85,22.07 66.85,20.93 65.63,19.71 65.63,19.1 65.61,19.08 64.85,19.08
N12962926 on TOP (solid shape): 73.91,24.05 74.07,24.05 74.14,23.98 74.14,23.32 69.37,23.32 69.29,23.39 69.29,24.03 69.34,24.08 73.89,24.08
N12962926 on BOTTOM: 72.49,24.16 72.77,24.16 74.83,22.1 74.83,17.78 74.52,17.48 73.81,17.48 73.81,18.14 73.94,18.26 74.22,18.26 74.57,18.62 74.57,20.52 74.04,21.06 74.04,21.69 72.29,23.44 72.29,23.95
N12962950 on TOP (solid shape): 68.96,23.09 70.61,23.09 70.64,23.06 70.64,22.81 68.96,22.81 68.88,22.73 68.68,22.73 68.61,22.81 68.61,23.16 68.68,23.24 68.81,23.24
N12962950 on TOP: 62.28,25.07 67.64,25.07 68.87,23.84 68.87,22.62 68.83,22.58 68.83,21.06 68.17,21.06 68.05,21.18 68.05,23.77 67.36,24.46 62.36,24.46 62.28,24.54
N12963022 on TOP: 59.49,26.77 61.04,26.77 61.26,27 61.26,27.69 61.32,27.74 62.2,27.74 62.23,27.71 62.23,26.77 61.9,26.44 59.54,26.44 59.44,26.54 59.44,26.72
N12963250 on TOP: 62.23,23.67 64.52,23.67 64.82,23.37 64.82,18.85 65.46,18.21 67.03,18.21 67.67,17.58 73.46,17.58 74.68,18.8 74.68,24.1 74.47,24.31 74.47,24.59 74.55,24.59 74.93,24.21 74.93,18.59 73.51,17.17 67.01,17.17 66.7,17.48 65.23,17.48 64.24,18.47 64.24,22.38 63.5,23.11 62.28,23.11 62.23,23.16 62.2,23.16 62.2,23.65
N12963250 on BOTTOM: 66.6,18.34 68.17,18.34 68.83,17.68 68.83,16.94 68.81,16.92 68.4,16.92 67.89,17.42 66.6,17.42
N12963278 on TOP: 59.49,26.14 61.09,26.14 61.8,25.43 61.8,24.49 61.77,24.46 61.24,24.46 61.21,24.49 61.21,24.99 61.24,25.02 61.24,25.17 60.58,25.83 59.51,25.83 59.46,25.88 59.46,26.11
N12963330 on TOP: 59.44,25.45 60.3,25.45 60.73,25.02 60.73,24.36 61.44,23.65 61.7,23.65 61.72,23.62 61.72,23.04 61.01,23.04 60.99,23.06 60.99,23.44 59.44,24.99
N12967863 on BOTTOM: 51.36,24.99 52.6,26.24 54.91,26.24 55.07,26.09 55.07,25.73 54.94,25.6 52.73,25.6 51.97,24.84 51.97,24.71 51.77,24.51 51.51,24.51 51.36,24.66
N12982735 on BOTTOM: 5.68,10.07 8.56,7.19 8.56,6.45 7.9,5.79 6.15,5.79 3.84,8.1 1.63,8.1 1.37,8.36 1.37,9.63 1.82,10.07
N12983558 on BOTTOM: 0.08,0.1 0.08,4.88 0.33,5.13 3.02,5.13 3.53,4.62 3.53,3.51 2.39,2.36 2.39,0.48 1.98,0.08 0.1,0.08
N12984078 on BOTTOM (solid shape): 6.6,16.46 6.6,11.58 6.48,11.46 3.84,11.46 3.84,15.98 4.45,16.59 6.48,16.59
N12984078 on BOTTOM (solid shape): 6.06,15.34 5.55,15.34 5.55,12.14 6.06,12.14 6.06,11.53 3.87,11.53 3.87,15.95 6.06,15.95
N12984078 on BOTTOM: 9.55,18.21 9.55,16.76 9.5,16.71 7.47,16.71 6.65,15.9 6.65,11.61 6.49,11.44 6.48,11.46 3.84,11.46 3.84,15.98 5.03,17.17 5.03,18.08 5.16,18.21
N12984082 on BOTTOM (solid shape): 11.81,16.41 11.81,11.66 11.66,11.51 9.09,11.51 9.04,11.56 9.04,16 10.69,16 11.23,16.54 11.68,16.54
N12984082 on BOTTOM: 11.2,16.51 11.2,18.21 12.75,18.21 12.75,16.64 11.86,15.75 11.86,14.61 13.49,12.98 13.49,11.61 13.39,11.51 9.09,11.51 9.04,11.56 9.04,16 10.69,16
N13015620 on TOP: 71.09,9.83 70.43,9.83 70.18,9.58 70.18,6.73 70.38,6.53 71.22,6.53 71.42,6.73 71.42,9.5
N13015620 on BOTTOM: 71.04,9.86 70.46,9.86 70.18,9.58 70.18,6.73 70.38,6.53 71.22,6.53 71.42,6.73 71.42,9.47

Small or netless copper shapes (teardrops, artwork), in the pictures only: 3 on TOP

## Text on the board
Ref Des/Silkscreen Bottom: 1937 | RD-848 Main | REV B | S/N
DEVICE_TYPE_BOTTOM: SLOTS | 13.  MATERIAL FR4 COPPER 2oz THICKNESS 0.062" | 14.  FAB HOUSE LOGO,DATE CODE TO BE IN SILK SCREEN ONLY.DO NOT USE COPPER. | PLEASE DELETE THESE PINS
User.9: FIGURE | FINISHED_SIZE | 18.0 | 25.0 | 30.0 | 40.0 | 41.0 | 50.0 | 68.0 | 1.0 | 33.465 | 70.0x30.0 | DRILL CHART: TOP to BOTTOM | ALL UNITS ARE IN MILS | TOLERANCE_DRILL | +3.0/-3.0 | +0.0/-0.0 | PLATED | NON-PLATED | QTY | 134 | 4 | 2 | 8 | 5 | 7 | 6
